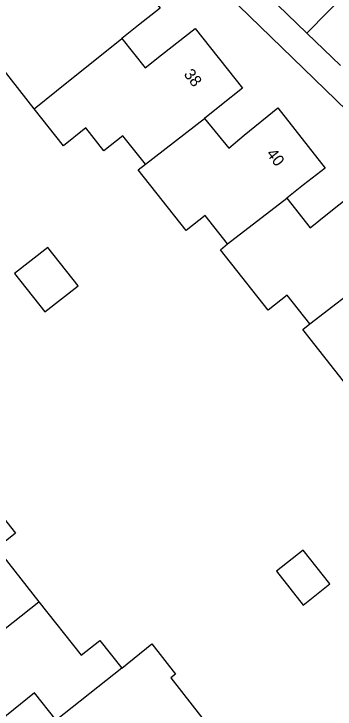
# Model space of a CAD drawing. Extents: x 157321 to 158827, y 386650 to 388532.
# Drawn here: x 157845.6 to 157873.4, y 387429.1 to 387489.3 of the extents above; entities that cross this region are included whole.
import ezdxf

# ---------------------------------------------------------------- set-up
doc = ezdxf.new("R2010")
doc.units = 0
for name, color, linetype in [('IMGEO_Pand', 7, 'Continuous'), ('IMGEO_Pand_nummerreeks', 7, 'Continuous'), ('IMGEO_Voetpad_open', 7, 'Continuous')]:
    doc.layers.add(name, color=color, linetype=linetype)

msp = doc.modelspace()

# ---------------------------------------------------------------- linework, layer by layer
at = {"layer": 'IMGEO_Pand'}
for points in [[(157847.855, 387494.099), (157849.927, 387491.519), (157851.35, 387492.67), (157854.168, 387494.95), (157858.299, 387489.761), (157856.427, 387488.291), (157854.983, 387487.157)], [(157847.39, 387481.078), (157843.224, 387486.343), (157844.153, 387487.078), (157842.144, 387489.617), (157842.786, 387490.125)], [(157854.983, 387487.157), (157856.988, 387484.607), (157858.413, 387485.739), (157861.322, 387488.019), (157865.423, 387482.845), (157863.62, 387481.412), (157862.14, 387480.236)], [(157847.39, 387481.078), (157849.332, 387482.625), (157854.983, 387487.157)], [(157857.027, 387476.278), (157855.076, 387478.744), (157853.432, 387477.443), (157851.871, 387479.416), (157849.924, 387477.875), (157847.39, 387481.078)], [(157862.14, 387480.236), (157864.231, 387477.677), (157865.577, 387478.775), (157868.481, 387481.144), (157872.575, 387475.946), (157870.72, 387474.484), (157869.266, 387473.338)], [(157857.027, 387476.278), (157862.14, 387480.236)], [(157864.14, 387469.38), (157862.195, 387471.838), (157860.543, 387470.531), (157856.393, 387475.776), (157857.027, 387476.278)], [(157869.266, 387473.338), (157871.284, 387470.787), (157872.78, 387471.978), (157875.59, 387474.216), (157879.703, 387469.042), (157878.855, 387468.371), (157876.37, 387466.405)], [(157864.14, 387469.38), (157869.266, 387473.338)], [(157871.266, 387462.466), (157869.308, 387464.94), (157867.664, 387463.639), (157863.514, 387468.884), (157864.14, 387469.38)], [(157845.69, 387466.811), (157848.312, 387463.498), (157851.186, 387465.771), (157848.564, 387469.085), (157845.69, 387466.811)], [(157871.266, 387462.466), (157876.37, 387466.405)], [(157878.403, 387455.537), (157876.452, 387458.003), (157874.808, 387456.702), (157870.639, 387461.97), (157871.266, 387462.466)], [(157843.819, 387446.813), (157845.762, 387444.36), (157844.126, 387443.063), (157847.794, 387438.433)], [(157868.364, 387441.068), (157870.675, 387438.147), (157872.985, 387439.975), (157870.674, 387442.896), (157868.364, 387441.068)], [(157839.411, 387431.832), (157847.794, 387438.433)], [(157847.794, 387438.433), (157851.464, 387433.8), (157853.077, 387435.077), (157854.979, 387432.676)], [(157854.979, 387432.676), (157857.587, 387434.787), (157859.641, 387432.18), (157859.211, 387431.841), (157862.72, 387427.386), (157858.965, 387424.329)], [(157854.979, 387432.676), (157849.307, 387428.187)], [(157849.307, 387428.187), (157847.41, 387430.562), (157843.144, 387427.129), (157839.411, 387431.832)]]:
    msp.add_lwpolyline(points, dxfattribs=at)
at = {"layer": 'IMGEO_Voetpad_open'}
for points in [[(157842.827, 387511.58), (157854.778, 387500), (157901.636, 387454.595)], [(157870.986, 387487.615), (157866.787, 387491.719)], [(157874.72, 387491.417), (157870.986, 387487.615)], [(157873.909, 387484.817), (157870.986, 387487.615)]]:
    msp.add_lwpolyline(points, dxfattribs=at)

# ---------------------------------------------------------------- texts
at = {"layer": 'IMGEO_Pand_nummerreeks'}
for s, rotation, p in [('38', 308.40094, (157860.291, 387484.04)), ('40', 308.22434, (157867.442, 387477.163))]:
    msp.add_text(s, height=1, rotation=rotation, dxfattribs=at).set_placement(p)

doc.saveas('drawing.dxf')
